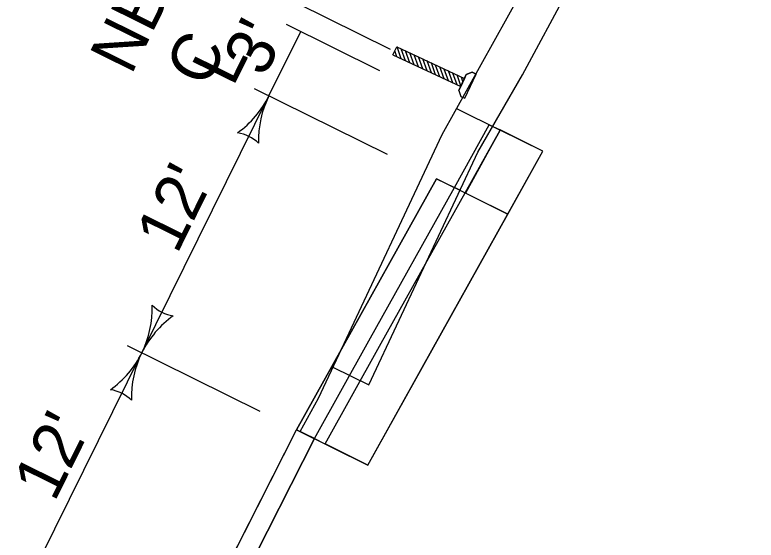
# Model space of a CAD drawing. Extents: x 14104283 to 14129344, y 8637090 to 8673339.
# Drawn here: x 14118264.5 to 14118388.7, y 8668626.6 to 8668714.6 of the extents above; entities that cross this region are included whole.
import ezdxf

# ---------------------------------------------------------------- set-up
doc = ezdxf.new("R2010")
doc.units = 0
for name, color, linetype in [('Cell', 7, 'Continuous'), ('Default', 7, 'Continuous'), ('dsnCellElements', 7, 'Continuous'), ('dsnShadingPaved', 7, 'Continuous'), ('dsnStgShadingPrevPav', 7, 'Continuous'), ('dsnTextFinalPlan', 7, 'Continuous'), ('TC_Subbase', 7, 'Continuous'), ('TC_SubgradeTreatment', 7, 'Continuous'), ('TC_SubstrataExistingPavement', 7, 'Continuous'), ('Terrain', 7, 'Continuous')]:
    doc.layers.add(name, color=color, linetype=linetype)

# ---------------------------------------------------------------- blocks, each defined once
blk = doc.blocks.new('LT')
at = {"layer": 'dsnCellElements'}
for centre, radius, start, end in [((-3.564, 0), 1.642, 342.2666, 17.7333), ((0, 4.25), 4.25, 241.9275, 270), ((0, -4.25), 4.25, 90, 118.0725)]:
    blk.add_arc(centre, radius, start, end, dxfattribs=at)

msp = doc.modelspace()

# ---------------------------------------------------------------- linework, layer by layer
at = {"layer": 'Cell'}
for p, q in [((14118327.84, 8668707.89), (14118328.47, 8668709.24)), ((14118328.47, 8668709.24), (14118339.81, 8668703.94)), ((14118329.23, 8668707.24), (14118328.52, 8668709.21)), ((14118327.84, 8668707.89), (14118339.18, 8668702.6)), ((14118328.51, 8668707.58), (14118328.15, 8668708.57)), ((14118329.95, 8668706.91), (14118329.24, 8668708.88)), ((14118330.67, 8668706.57), (14118329.95, 8668708.54)), ((14118331.39, 8668706.24), (14118330.67, 8668708.21)), ((14118332.11, 8668705.9), (14118331.39, 8668707.87)), ((14118332.83, 8668705.56), (14118332.11, 8668707.54)), ((14118333.55, 8668705.23), (14118332.83, 8668707.2)), ((14118334.27, 8668704.89), (14118333.55, 8668706.87)), ((14118334.98, 8668704.56), (14118334.27, 8668706.53)), ((14118335.7, 8668704.22), (14118334.99, 8668706.19)), ((14118336.42, 8668703.89), (14118335.71, 8668705.86)), ((14118337.14, 8668703.55), (14118336.42, 8668705.52)), ((14118337.86, 8668703.22), (14118337.14, 8668705.19)), ((14118338.58, 8668702.88), (14118337.86, 8668704.85)), ((14118339.23, 8668702.72), (14118338.58, 8668704.52)), ((14118338.87, 8668701.93), (14118340.12, 8668704.62)), ((14118339.57, 8668703.44), (14118339.3, 8668704.18)), ((14118340.12, 8668704.62), (14118339.81, 8668703.94)), ((14118339.89, 8668700.63), (14118341.77, 8668704.67)), ((14118339.89, 8668700.63), (14118341.77, 8668704.67)), ((14118341.1, 8668704.98), (14118340.12, 8668704.62)), ((14118340.12, 8668704.62), (14118341.1, 8668704.98)), ((14118341.77, 8668704.67), (14118341.1, 8668704.98)), ((14118341.1, 8668704.98), (14118341.77, 8668704.67)), ((14118339.81, 8668703.94), (14118339.18, 8668702.6)), ((14118339.18, 8668702.6), (14118338.87, 8668701.93)), ((14118338.87, 8668701.93), (14118339.22, 8668700.94)), ((14118338.87, 8668701.93), (14118339.22, 8668700.94)), ((14118339.22, 8668700.94), (14118339.89, 8668700.63)), ((14118339.22, 8668700.94), (14118339.89, 8668700.63))]:
    msp.add_line(p, q, dxfattribs=at)
at = {"layer": 'Default'}
for p, q in [((14118335.14, 8668687.15), (14118338.13, 8668685.68)), ((14118314.68, 8668643.65), (14118311.69, 8668645.12))]:
    msp.add_line(p, q, dxfattribs=at)
for points in [[(14118311.69, 8668645.12), (14118320.83, 8668661.5), (14118335.14, 8668687.15)], [(14118314.68, 8668643.65), (14118323.81, 8668660.02), (14118338.13, 8668685.68)]]:
    msp.add_lwpolyline(points, dxfattribs=at)
at = {"layer": 'dsnShadingPaved'}
for points in [[(14118338.13, 8668685.68), (14118343.98, 8668696.17), (14118345.79, 8668695.32), (14118340, 8668684.75)], [(14118347.09, 8668681.24), (14118352.95, 8668691.74), (14118345.77, 8668695.28), (14118339.92, 8668684.79)], [(14118311.69, 8668645.12), (14118323.63, 8668639.18), (14118347.09, 8668681.24), (14118335.14, 8668687.15)]]:
    msp.add_lwpolyline(points, close=True, dxfattribs=at)
at = {"layer": 'dsnStgShadingPrevPav'}
msp.add_lwpolyline([(14118287.17, 8668596.29), (14118289.97, 8668602.25), (14118311.69, 8668645.12), (14118314.68, 8668643.65), (14118302.91, 8668620.41), (14118292.96, 8668600.77), (14118290.16, 8668594.81)], close=True, dxfattribs=at)
at = {"layer": 'dsnTextFinalPlan'}
for p, q in [((14118311.71, 8668716.59), (14118327.37, 8668708.85)), ((14118309.93, 8668713), (14118325.59, 8668705.26)), ((14118307.07, 8668701.03), (14118312.39, 8668711.79)), ((14118304.62, 8668702.25), (14118326.85, 8668691.25)), ((14118285.79, 8668658.01), (14118307.07, 8668701.03)), ((14118283.34, 8668659.22), (14118305.57, 8668648.23)), ((14118264.52, 8668614.98), (14118285.79, 8668658.01))]:
    msp.add_line(p, q, dxfattribs=at)
at = {"layer": 'TC_Subbase'}
for p, q in [((14118338.5, 8668698.88), (14118345.77, 8668695.28)), ((14118314.68, 8668643.65), (14118316.42, 8668642.78))]:
    msp.add_line(p, q, dxfattribs=at)
msp.add_lwpolyline([(14118316.47, 8668642.76), (14118325.61, 8668659.13), (14118345.77, 8668695.28)], dxfattribs=at)
at = {"layer": 'TC_SubgradeTreatment'}
for p, q in [((14118352.95, 8668691.74), (14118345.79, 8668695.32)), ((14118323.63, 8668639.18), (14118316.47, 8668642.76))]:
    msp.add_line(p, q, dxfattribs=at)
msp.add_lwpolyline([(14118323.63, 8668639.18), (14118332.76, 8668655.55), (14118352.95, 8668691.74)], dxfattribs=at)
at = {"layer": 'TC_SubstrataExistingPavement'}
msp.add_line((14118314.68, 8668643.65), (14118311.69, 8668645.12), dxfattribs=at)
for points in [[(14118317.8, 8668655.57), (14118323.78, 8668652.61), (14118328.88, 8668663.48), (14118342.07, 8668691.57), (14118349.51, 8668704.57), (14118365.08, 8668733.42), (14118363.29, 8668734.31)], [(14118292.96, 8668600.77), (14118302.91, 8668620.41), (14118314.68, 8668643.65)]]:
    msp.add_lwpolyline(points, dxfattribs=at)
at = {"layer": 'Terrain'}
for points in [[(14118312.3, 8668644.82), (14118315.38, 8668650.41), (14118318.4, 8668656.85), (14118336.09, 8668694.53), (14118351.32, 8668721.95), (14118359.1, 8668736.38), (14118371.8, 8668757.81), (14118379.34, 8668769.44), (14118400.6, 8668797.95), (14118408.04, 8668806.8), (14118456.58, 8668898.64)], [(14118289.97, 8668602.25), (14118299.92, 8668621.89), (14118311.69, 8668645.12)]]:
    msp.add_lwpolyline(points, dxfattribs=at)

# ---------------------------------------------------------------- block references
at = {"layer": 'dsnTextFinalPlan'}
for p, xscale, yscale, rotation in [((14118307.07, 8668701.03), 3.942400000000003, 3.9424000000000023, 63.69110745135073), ((14118285.79, 8668658.01), 3.942400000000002, 3.9424000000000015, -116.30889254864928), ((14118285.79, 8668658.01), 3.942400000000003, 3.9424000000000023, 63.69110745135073)]:
    msp.add_blockref('LT', p, dxfattribs=dict(at, xscale=xscale, yscale=yscale, rotation=rotation))

# ---------------------------------------------------------------- texts
for s, p in [('NB', (14118284, 8668704.36)), ("3'", (14118306.31, 8668703.97)), ('C', (14118296.63, 8668702.15)), ('L', (14118301.07, 8668702.4)), ("12'", (14118291.67, 8668674.37)), ("12'", (14118271.15, 8668632.86))]:
    msp.add_text(s, height=8, rotation=63.6911, dxfattribs=at).set_placement(p)

doc.saveas('drawing.dxf')
